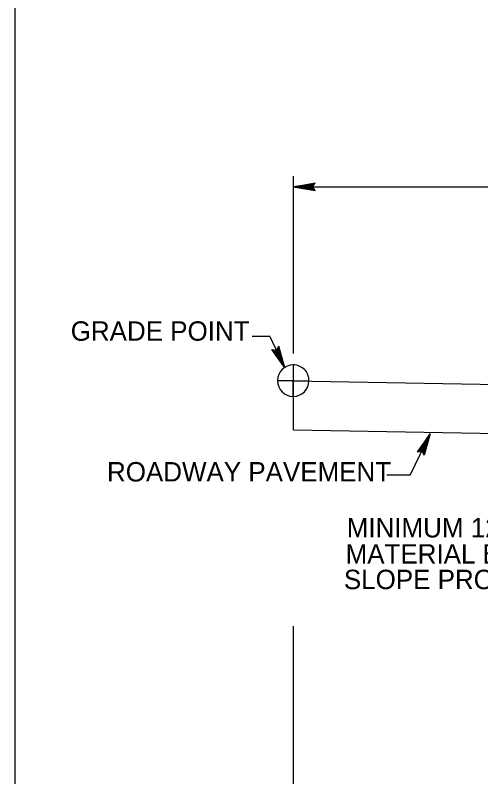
# Model space of a CAD drawing. Extents: x 1553195 to 1553792, y 810516 to 810787.
# Drawn here: x 1553739.44 to 1553752.03, y 810723.14 to 810743.73 of the extents above; entities that cross this region are included whole.
import ezdxf

# ---------------------------------------------------------------- set-up
doc = ezdxf.new("R2010")
doc.units = 0
doc.layers.add('Old_Level_28', color=7, linetype='Continuous')

msp = doc.modelspace()

# ---------------------------------------------------------------- linework, layer by layer
at = {"layer": 'Old_Level_28'}
for p, q in [((1553746.957, 810739.379), (1553746.957, 810734.581)), ((1553746.957, 810739.095), (1553747.552, 810739.197)), ((1553746.957, 810739.095), (1553747.539, 810739.181)), ((1553747.477, 810739.095), (1553747.552, 810739.197)), ((1553747.53, 810739.168), (1553746.957, 810739.095)), ((1553746.957, 810739.095), (1553747.519, 810739.152)), ((1553747.508, 810739.137), (1553746.957, 810739.095)), ((1553746.957, 810739.095), (1553747.497, 810739.123)), ((1553747.486, 810739.108), (1553746.957, 810739.095)), ((1553746.957, 810739.095), (1553752.957, 810739.095)), ((1553746.957, 810739.095), (1553747.552, 810738.988)), ((1553747.539, 810739.004), (1553746.957, 810739.095)), ((1553746.957, 810739.095), (1553747.53, 810739.017)), ((1553747.519, 810739.032), (1553746.957, 810739.095)), ((1553746.957, 810739.095), (1553747.508, 810739.048)), ((1553747.497, 810739.061), (1553746.957, 810739.095)), ((1553746.957, 810739.095), (1553747.486, 810739.077)), ((1553747.477, 810739.095), (1553746.957, 810739.095)), ((1553747.552, 810738.988), (1553747.477, 810739.095)), ((1553745.848, 810735.055), (1553746.321, 810735.055)), ((1553746.732, 810734.2), (1553746.321, 810735.055)), ((1553746.732, 810734.2), (1553746.377, 810734.691)), ((1553746.377, 810734.691), (1553746.508, 810734.667)), ((1553746.397, 810734.689), (1553746.732, 810734.2)), ((1553746.732, 810734.2), (1553746.415, 810734.687)), ((1553746.432, 810734.68), (1553746.732, 810734.2)), ((1553746.732, 810734.2), (1553746.452, 810734.678)), ((1553746.471, 810734.676), (1553746.732, 810734.2)), ((1553746.732, 810734.2), (1553746.49, 810734.674)), ((1553746.508, 810734.667), (1553746.566, 810734.782)), ((1553746.508, 810734.667), (1553746.732, 810734.2)), ((1553746.517, 810734.684), (1553746.732, 810734.2)), ((1553746.732, 810734.2), (1553746.524, 810734.7)), ((1553746.533, 810734.718), (1553746.732, 810734.2)), ((1553746.732, 810734.2), (1553746.543, 810734.733)), ((1553746.55, 810734.752), (1553746.732, 810734.2)), ((1553746.732, 810734.2), (1553746.559, 810734.767)), ((1553746.732, 810734.2), (1553746.566, 810734.782)), ((1553746.957, 810734.277), (1553746.957, 810733.85)), ((1553746.957, 810733.85), (1553746.53, 810733.848)), ((1553746.957, 810733.85), (1553752.95, 810733.739)), ((1553746.957, 810733.85), (1553746.957, 810733.85)), ((1553746.957, 810733.424), (1553746.957, 810733.85)), ((1553746.957, 810733.85), (1553747.383, 810733.85)), ((1553746.968, 810732.522), (1553746.968, 810733.85)), ((1553746.968, 810732.522), (1553752.959, 810732.41)), ((1553750.123, 810731.297), (1553750.663, 810732.415)), ((1553750.663, 810732.415), (1553750.308, 810731.924)), ((1553750.328, 810731.926), (1553750.663, 810732.415)), ((1553750.663, 810732.415), (1553750.346, 810731.928)), ((1553750.363, 810731.934), (1553750.663, 810732.415)), ((1553750.663, 810732.415), (1553750.383, 810731.937)), ((1553750.402, 810731.939), (1553750.663, 810732.415)), ((1553750.663, 810732.415), (1553750.422, 810731.941)), ((1553750.439, 810731.948), (1553750.663, 810732.415)), ((1553750.448, 810731.93), (1553750.663, 810732.415)), ((1553750.663, 810732.415), (1553750.455, 810731.914)), ((1553750.464, 810731.897), (1553750.663, 810732.415)), ((1553750.663, 810732.415), (1553750.475, 810731.881)), ((1553750.481, 810731.864), (1553750.663, 810732.415)), ((1553750.663, 810732.415), (1553750.49, 810731.848)), ((1553750.663, 810732.415), (1553750.497, 810731.832)), ((1553750.308, 810731.924), (1553750.439, 810731.948)), ((1553750.439, 810731.948), (1553750.497, 810731.832)), ((1553750.123, 810731.297), (1553749.49, 810731.297)), ((1553746.957, 810727.211), (1553746.957, 810707.692))]:
    msp.add_line(p, q, dxfattribs=at)
msp.add_lwpolyline([(1553739.439, 810764.018), (1553791.973, 810764.018), (1553791.973, 810694.817), (1553739.439, 810694.817)], close=True, dxfattribs=at)
for start, end in [(90.1432, 179.2898), (359.8329, 90.1432), (180.2626, 269.8568), (269.8568, 359.8329)]:
    msp.add_arc((1553746.957, 810733.851), 0.427, start, end, dxfattribs=at)

# ---------------------------------------------------------------- texts
for s, p in [('GRADE POINT', (1553740.94, 810734.93)), ('ROADWAY PAVEMENT', (1553741.922, 810731.124)), ('MINIMUM 12" HEIGHT EXPANSION JOINT', (1553748.405, 810729.611)), ('MATERIAL BETWEEN FACE OF PIER AND', (1553748.374, 810728.904)), ('SLOPE PROTECTION TOE.', (1553748.328, 810728.213))]:
    msp.add_text(s, height=0.52493, dxfattribs=at).set_placement(p)

doc.saveas('drawing.dxf')
